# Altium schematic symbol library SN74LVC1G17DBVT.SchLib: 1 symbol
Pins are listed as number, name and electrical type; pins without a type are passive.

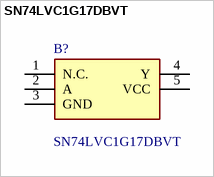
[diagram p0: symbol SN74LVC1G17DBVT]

## SN74LVC1G17DBVT
designator B?
Single Schmitt-Trigger Buffer; Manufacturer_Name: Texas Instruments; Geometry.Height: 1.45mm
footprint SOT95P280X145-5N
pins: 1 N.C., 2 A, 3 GND, 4 Y, 5 VCC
